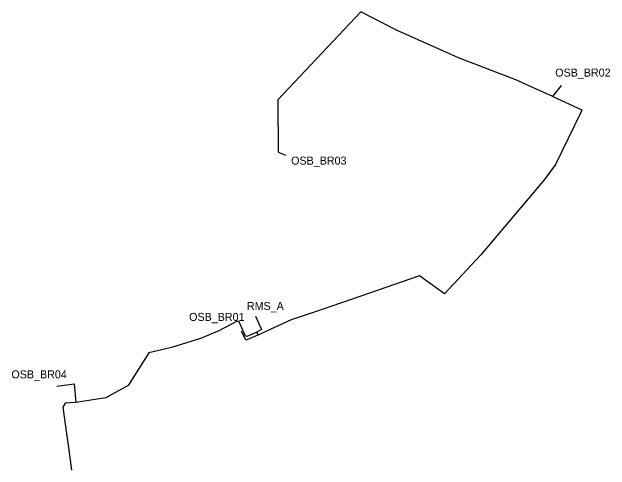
# Model space of a CAD drawing. Extents: x 607880 to 609373, y 4066209 to 4067354.
import ezdxf

# ---------------------------------------------------------------- set-up
doc = ezdxf.new("R2010")
doc.units = 0
for name, color, linetype in [('GW_NODETX', 7, 'Continuous'), ('ST04', 7, 'Continuous'), ('ST06', 7, 'Continuous'), ('ST12', 7, 'Continuous')]:
    doc.layers.add(name, color=color, linetype=linetype)

msp = doc.modelspace()

# ---------------------------------------------------------------- linework, layer by layer
at = {"layer": 'ST04'}
msp.add_line((609230.2, 4067142.5), (609252.1, 4067170.5), dxfattribs=at)
for points in [[(609184, 4067163.2), (609137.8, 4067184.2), (608994.9, 4067239), (608840.1, 4067308.5), (608750.8, 4067354), (608543.7, 4067134.5), (608544.2, 4067003.5)], [(608544.2, 4067003.5), (608546.2, 4067002.6), (608563.2, 4066996)], [(608488, 4066543.2), (608464, 4066533.5), (608452.8, 4066555.5)], [(607991.6, 4066418.2), (608035.1, 4066424), (608039.2, 4066377.2)]]:
    msp.add_lwpolyline(points, dxfattribs=at)
at = {"layer": 'ST06'}
msp.add_line((609230.2, 4067142.5), (609184, 4067163.2), dxfattribs=at)
for points in [[(609230.2, 4067142.5), (609303.2, 4067109.5), (609299.9, 4067101.2), (609236.8, 4066972.8), (609209.6, 4066935), (609050.2, 4066747), (608959.9, 4066649.2), (608897.5, 4066693.8), (608729.6, 4066635.5), (608649.2, 4066608.5), (608577.3, 4066583.8), (608494.1, 4066546.2)], [(608491.2, 4066553.2), (608494.1, 4066546.2), (608488, 4066543.2)]]:
    msp.add_lwpolyline(points, dxfattribs=at)
at = {"layer": 'ST12'}
for p, q in [((608488, 4066593.2), (608502.8, 4066559.8)), ((608502.8, 4066559.8), (608491.2, 4066553.2))]:
    msp.add_line(p, q, dxfattribs=at)
for points in [[(608491.2, 4066553.2), (608466.1, 4066542.2), (608462.8, 4066543), (608447.2, 4066578.8), (608442, 4066580.5), (608396.6, 4066557), (608350.2, 4066537.8), (608278.1, 4066515), (608221.4, 4066501.5), (608169.9, 4066420), (608114.2, 4066389.5), (608039.2, 4066377.2)], [(608039.2, 4066377.2), (608012.4, 4066375.5), (608006.7, 4066366), (608012.6, 4066323.6), (608020.5, 4066265), (608028, 4066208.6)]]:
    msp.add_lwpolyline(points, dxfattribs=at)

# ---------------------------------------------------------------- texts
at = {"layer": 'GW_NODETX'}
for s, p in [('OSB_BR02', (609236.4, 4067192.3)), ('OSB_BR03', (608576.9, 4066972.3)), ('RMS_A', (608466.4, 4066608.8)), ('OSB_BR01', (608322.2, 4066581.5)), ('OSB_BR04', (607878.4, 4066437.9))]:
    msp.add_text(s, height=20, dxfattribs=at).set_placement(p)

doc.saveas('drawing.dxf')
